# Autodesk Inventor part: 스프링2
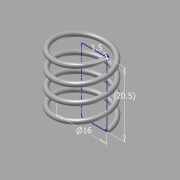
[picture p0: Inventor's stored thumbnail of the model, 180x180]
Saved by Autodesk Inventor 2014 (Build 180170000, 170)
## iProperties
Created: 2015-07
Part Number: 스프링2
Material: 강철, 연강
Document SubType Name: Modeling
Designer: Administrator
Density: 7.86 g/cm^3
Appearance: 강철
Mass: 2.74935 g
Surface Area: 9.46899 cm^2
Volume: 0.349791 cm^3
Author: Administrator
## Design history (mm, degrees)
sketch "스케치1"
  geometry: L1 (0, 0)-(-8, 0); L2 (-8, 0)-(-8, -20.5); L3 (-8, -20.5)-(0, -20.5); L4 (0, -20.5)-(0, 0); C1 r 0.75 at (-8, 0)
  constraints: 8 end point, 2 parallel, 1 centre point, 1 coincident, 1 horizontal, 1 perpendicular
  dimensions: "d0" = 16 diameter of L2 L4; "d1" = 20.5 distance of L1.end L2.end (derived); "d2" = 1.5 diameter of C1
feature "코일1" pitch "d3" = 10; turns "d5" = 4; dims "d4" = 20.5 (= d1), "d6" = 0, angle "d7" = 90 deg, angle "d8" = 90 deg, "d9" = 0, "d10" = 0
sketch "스케치2"
  geometry: L1 (7.25, 0)-(8.75, 0) reference; 1 further point
  constraints: 1 horizontal alignment
extrude "돌출1" cut sketch "스케치2" stored distance "d11" = 10; taper "d12" = 0 deg
node "작업 평면1"
sketch "스케치3"
  geometry: L1 (8.75, 0)-(7.25, 0) reference; 1 further point
  constraints: 1 horizontal alignment
extrude "돌출2" cut sketch "스케치3" stored distance "d13" = 10; taper "d14" = 0 deg
node "솔리드1"
node "절단 모서리 투영1"
node "절단 모서리 투영2"
